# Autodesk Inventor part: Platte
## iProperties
Created: 2007-01
Material: Standard
Description: Blech lt. Tab.
Document SubType Name: Blech
Designer: R.Pilz
Title: Platte
Author: R.Pilz
ArtNrPrefix: HZ
ArtNrAuto: 0
EDVNum=ArtNr: 0
Bez=Mat: 0
ArtNrBackSpace: 0
EDVNrBackSpace: 0
EDVNrAuto: 0
ProdGruppe: ÜKWW
ProdBezeichnung: Blende
ArtNr: HZG24TE20
EDVNr: L4321
KommaZuschnitt: 0
Zeichnungsnummer: 0G24 TE ST
Konstrukteur: R.Pilz
Erstellungsdatum: 10.01.2007
GesGewicht: 1,2kg
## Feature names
1. Abgeleiteter Körper1 [Tagging]
